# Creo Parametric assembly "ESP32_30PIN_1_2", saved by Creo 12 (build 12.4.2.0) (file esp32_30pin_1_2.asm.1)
Units: Custom; MM, KILOGRAM, SECS

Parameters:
  PTC_WM_ITERATION = "0"
  PTC_WM_VERSION = "-.0"
  PTC_WM_LIFECYCLE_STATE = "In Work"
  PTC_WM_LIFECYCLE = "MO_CADDocument"
  PTC_WM_CREATED_BY = "Maximilian Roepper (Z0017RMS: MO)"
  PTC_WM_CREATED_ON = "18-Sep-26 11:36:42 AM"
  PTC_WM_MODIFIED_BY = "Maximilian Roepper (Z0017RMS: MO)"
  PTC_WM_MODIFIED_ON = "18-Sep-26 11:36:46 AM"
  PDMLINKNUMBER = "PDM000071455280"
  PTC_WM_NUMBER = "PDM000071455280"

Other parameters: WEIGHT, WEIGHT_FACTOR, WEIGHT_ADD, MC_ERRORS, SUPPLIER

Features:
  1. coordinate system
  2. imported feature
  3. component "ESP32_30PIN_1_2_3"

Other named items: DRW_VIEW_ORG, ROUGH-GROB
